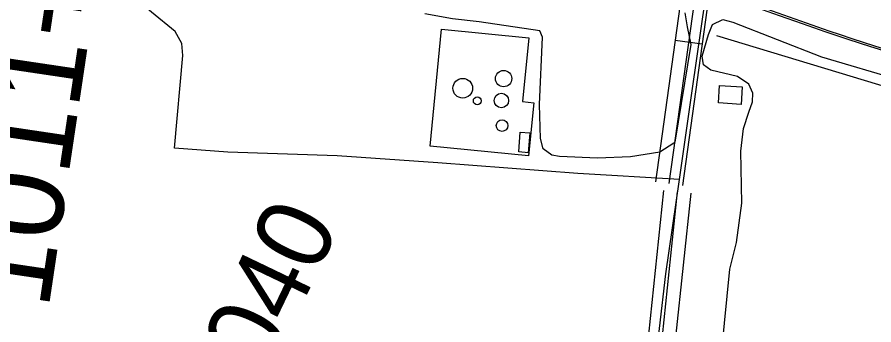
# Model space of a CAD drawing. Extents: x 3424494 to 3462436, y 522220 to 547718.
# Drawn here: x 3441427 to 3442371, y 536899 to 537239 of the extents above; entities that cross this region are included whole.
import ezdxf

# ---------------------------------------------------------------- set-up
doc = ezdxf.new("R2010")
doc.units = 0
for name, color, linetype in [('V-BLDG-OTLN', 7, 'Continuous'), ('V-DOMW-TANK', 7, 'Continuous'), ('V-DTCH-CNTR', 7, 'Continuous'), ('V-RAIL-TRAK', 7, 'Continuous'), ('V-RIVR-RANG-IDEN', 7, 'Continuous'), ('V-ROAD-CNTR', 7, 'Continuous'), ('V-SITE-OTLN', 7, 'Continuous'), ('V-SITE-VEGE', 7, 'Continuous'), ('V-SURV-IDEN', 7, 'Continuous'), ('V-TOPO-SHOR', 7, 'Continuous')]:
    doc.layers.add(name, color=color, linetype=linetype)

msp = doc.modelspace()

# ---------------------------------------------------------------- linework, layer by layer
at = {"layer": 'V-BLDG-OTLN'}
for points in [[(3442224.52, 537142.55), (3442199.38, 537144.11), (3442200.58, 537163.44), (3442225.71, 537161.89)], [(3441979.69, 537090.38), (3441981.21, 537111.86), (3441991.61, 537111.13), (3441990.04, 537089.02)]]:
    msp.add_lwpolyline(points, close=True, dxfattribs=at)
at = {"layer": 'V-DOMW-TANK'}
for centre, radius in [((3441962.79, 537170.94), 9.01), ((3441917.87, 537160.36), 10.83), ((3441960.39, 537146.77), 7.98), ((3441933.84, 537146.41), 4.35), ((3441961.09, 537119.08), 6.36)]:
    msp.add_circle(centre, radius, dxfattribs=at)
at = {"layer": 'V-DTCH-CNTR'}
for points in [[(3442156.41, 537059.79), (3442044.42, 537066.44), (3441890.29, 537077.98), (3441779.63, 537085.94), (3441659.06, 537090.01), (3441600.44, 537094.34), (3441609.67, 537196.43), (3441608.43, 537209.61), (3441601.27, 537222.84), (3441575.05, 537244.1), (3441559.97, 537256.71), (3441556.05, 537262.01), (3441551.51, 537273.24), (3441550.99, 537294.99), (3441564.1, 537386.51), (3441575.15, 537464.2), (3441575.23, 537477.38), (3441569.38, 537489.94), (3441543.82, 537511.85), (3441504.45, 537537.8), (3441489.35, 537546.47), (3441472.25, 537551.85), (3441430.77, 537557.39)], [(3442025.43, 535907), (3442043.96, 536084.93), (3442077.24, 536392.14), (3442110.43, 536686.13), (3442127.54, 536835.23), (3442141.38, 536955.79), (3442156.41, 537059.79), (3442170.5, 537157.3), (3442185.06, 537259.45), (3442186.67, 537269.82), (3442192, 537342.11), (3442196.63, 537413.03), (3442201, 537442.91), (3442207.4, 537465.12), (3442218.82, 537501.96)]]:
    msp.add_lwpolyline(points, dxfattribs=at)
at = {"layer": 'V-RAIL-TRAK'}
msp.add_lwpolyline([(3442398.59, 537196.3), (3442367.41, 537205.92), (3442342.17, 537214.15), (3442316.99, 537222.58), (3442291.88, 537231.21), (3442266.83, 537240.04), (3442241.86, 537249.06), (3442216.96, 537258.28), (3442186.67, 537269.82), (3442167.38, 537277.3), (3442144.59, 537285.89), (3442121.87, 537294.67), (3442099.23, 537303.63), (3442076.65, 537312.78), (3442054.16, 537322.12), (3442031.74, 537331.64), (3442009.4, 537341.34), (3441987.14, 537351.23), (3441964.96, 537361.3), (3441942.87, 537371.55), (3441920.86, 537381.98), (3441898.94, 537392.59), (3441873.71, 537404.66)], dxfattribs=at)
at = {"layer": 'V-ROAD-CNTR'}
msp.add_line((3442181.38, 537208.91), (3442151.66, 537213.04), dxfattribs=at)
for points in [[(3442192.91, 537510.19), (3442130.03, 537057.18)], [(3442207.76, 537508.13), (3442144.89, 537055.12)], [(3442222.62, 537506.07), (3442159.75, 537053.05)], [(3442139, 537047.65), (3442122.4, 536888.93), (3442065.43, 536351.07), (3442014.28, 535923.14)], [(3442153.92, 537046.09), (3442137.32, 536887.36), (3442080.33, 536349.39), (3442027.53, 535907.63)], [(3442168.84, 537044.53), (3442152.24, 536885.79), (3442095.24, 536347.71), (3442044.36, 535922.01)]]:
    msp.add_lwpolyline(points, dxfattribs=at)
msp.add_arc((3443559.04, 540863.05), 3844.17, 245.08995, 257.73319, dxfattribs=at)
at = {"layer": 'V-SITE-OTLN'}
msp.add_lwpolyline([(3441881.95, 537096.56), (3441894.57, 537225.45), (3441990.48, 537216.06), (3441983.58, 537145.58), (3441995.98, 537144.36), (3441990.27, 537085.95)], close=True, dxfattribs=at)
at = {"layer": 'V-SITE-VEGE'}
for points in [[(3442162.26, 537243.43), (3442164.95, 537228.04), (3442169.02, 537208.46), (3442151.56, 537101.01), (3442150.16, 537099.62), (3442134.73, 537089.94), (3442102.56, 537084.56), (3442066.24, 537083.4), (3442024.34, 537085.06), (3442015.97, 537086.51), (3442006.23, 537093.56), (3442003.51, 537104.75), (3442002.36, 537142.48), (3442005.63, 537216.49), (3442002.88, 537223.5), (3441935.89, 537233.71), (3441906.58, 537236.69), (3441875.88, 537242.47)], [(3442203.17, 536871.58), (3442212.13, 536960.93), (3442219.3, 536990.21), (3442225.16, 537033.48), (3442224.14, 537090.76), (3442227.09, 537115.89), (3442232.8, 537134.01), (3442237.06, 537145.16), (3442237.12, 537154.94), (3442233, 537164.74), (3442220.48, 537173.2), (3442191.19, 537180.38), (3442182.84, 537186.02), (3442181.51, 537195.81), (3442188.65, 537219.51), (3442192.91, 537230.65), (3442204.12, 537236.17), (3442215.28, 537233.31), (3442312.81, 537194.96), (3442487.1, 537143.55)]]:
    msp.add_lwpolyline(points, dxfattribs=at)
at = {"layer": 'V-TOPO-SHOR'}
msp.add_lwpolyline([(3442197.23, 537218.37), (3442538.2, 537115.13), (3442861.59, 537038.01), (3443254.71, 536987.4)], dxfattribs=at)

# ---------------------------------------------------------------- texts
at = {"layer": 'V-RIVR-RANG-IDEN'}
msp.add_text('D-040', height=83, rotation=64.34733, dxfattribs=at).set_placement((3441652.17, 536736.65))
at = {"layer": 'V-SURV-IDEN'}
msp.add_text('1011+70.7', height=100, rotation=81.52535, dxfattribs=at).set_placement((3441461.4, 536915.14))

doc.saveas('drawing.dxf')
